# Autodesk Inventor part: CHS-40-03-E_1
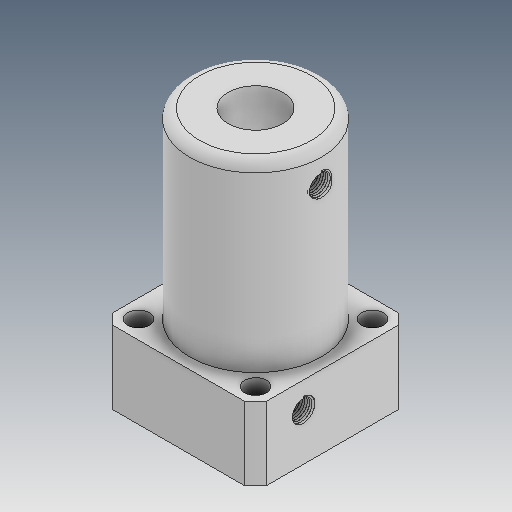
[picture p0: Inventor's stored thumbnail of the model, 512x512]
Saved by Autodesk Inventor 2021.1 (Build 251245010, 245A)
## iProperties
Created: 2019-04
Part Number: CHS-40-03-E_1
Material: Ogólny
Document SubType Name: Modeling
Designer: user
Density: 1 g/cm^3
Appearance: Domyślna
Author: user
Revision Number: ÈÎºÎ
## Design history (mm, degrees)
feature "ÊäÈë1"
node "Bryła1"
